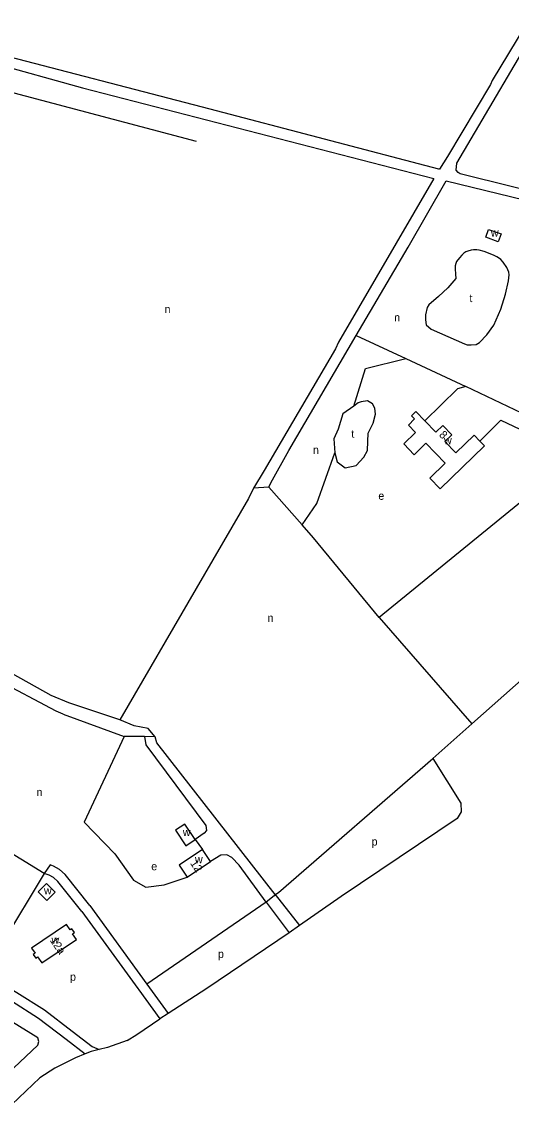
# Model space of a CAD drawing. Extents: x 156521 to 159067, y 384230 to 386095.
# Drawn here: x 158368 to 158613, y 384239 to 384783 of the extents above; entities that cross this region are included whole.
import ezdxf

# ---------------------------------------------------------------- set-up
doc = ezdxf.new("R2010")
doc.units = 0
for name, color, linetype in [('BLT_Basislijn', 7, 'Continuous'), ('BLT_Bebouwing', 7, 'Continuous'), ('BLT_Centroide', 7, 'Continuous'), ('BLT_Huisnummer', 7, 'Continuous')]:
    doc.layers.add(name, color=color, linetype=linetype)

msp = doc.modelspace()

# ---------------------------------------------------------------- linework, layer by layer
at = {"layer": 'BLT_Basislijn'}
for p, q in [((158352.64, 384750.74), (158455.21, 384723.61)), ((158535.23, 384626.42), (158559.94, 384614.94)), ((158559.94, 384614.94), (158589.98, 384600.98)), ((158650.46, 384571.96), (158589.98, 384600.98)), ((158537.65, 384593.29), (158536.19, 384592.74)), ((158536.19, 384592.74), (158533.96, 384591.17)), ((158639.35, 384561.14), (158546.61, 384485.51)), ((158489.11, 384559.04), (158483.85, 384550.1)), ((158491.46, 384550.64), (158483.85, 384550.1)), ((158508.09, 384531.79), (158491.46, 384550.64)), ((158513.81, 384525.32), (158508.09, 384531.79)), ((158546.61, 384485.51), (158513.81, 384525.32)), ((158455.16, 384500), (158416.95, 384434.38)), ((158546.61, 384485.51), (158592.98, 384432.27)), ((158592.98, 384432.27), (158655.78, 384487.93)), ((158416.95, 384434.38), (158391.54, 384442.78)), ((158388.72, 384437.21), (158419.17, 384425.97)), ((158573.58, 384415.07), (158592.98, 384432.27)), ((158429.32, 384425.97), (158419.17, 384425.97)), ((158434.62, 384425.77), (158429.32, 384425.97)), ((158379.14, 384357.53), (158354.03, 384372.8)), ((158454.66, 384374.5), (158458.38, 384369.51)), ((158490.08, 384343.23), (158501.59, 384327.81)), ((158494.68, 384347.02), (158506.82, 384331.47)), ((158506.82, 384331.47), (158501.59, 384327.81)), ((158426.42, 384299.39), (158437.05, 384284.91))]:
    msp.add_line(p, q, dxfattribs=at)
for points in [[(158342.81, 384770.73), (158333.64, 384773.36), (158283.17, 384786.22), (158282.77, 384787.06), (158335.72, 384877.79), (158631, 384801.39), (158631.05, 384800.83), (158627.73, 384794.49), (158603.23, 384753.88), (158602.28, 384751.89), (158580.79, 384715.97), (158576.88, 384709.55), (158576.56, 384709.5), (158462.13, 384739.64), (158349.17, 384768.98)], [(158736.06, 384689.06), (158733.97, 384685.58), (158724.47, 384677.61), (158719.79, 384675.59), (158715, 384675.59), (158591.18, 384706.23), (158587.23, 384707.3), (158586.12, 384707.91), (158585.24, 384709.01), (158585.48, 384712.56), (158630.6, 384789.27), (158635.77, 384798.67), (158636.48, 384799.41), (158637.85, 384799.54), (158660.96, 384793.85), (158752.07, 384770.33)], [(158352.67, 384762.86), (158398.26, 384750.21), (158574.08, 384704.89)], [(158574.08, 384704.89), (158526.41, 384623.05), (158524.75, 384619.77), (158489.11, 384559.04)], [(158535.23, 384626.42), (158561.09, 384670.52), (158580.13, 384703.71), (158664.3, 384683.31), (158653.02, 384664.92)], [(158491.46, 384550.64), (158492.42, 384552.8), (158501.54, 384568.98), (158535.23, 384626.42)], [(158533.96, 384591.17), (158539.78, 384609.9), (158559.94, 384614.94)], [(158589.98, 384600.98), (158585.79, 384599.85), (158569.58, 384583.81)], [(158524.51, 384567.78), (158525.65, 384563.34), (158529.66, 384560.33), (158535.13, 384561.44), (158538.92, 384565.56), (158540.86, 384568.91), (158541.04, 384573.49), (158541.2, 384577.64), (158543.72, 384582.59), (158544.82, 384587.18), (158544.56, 384590.11), (158543.26, 384592.27), (158540.76, 384593.83), (158537.65, 384593.29)], [(158533.96, 384591.17), (158528.53, 384587.34), (158526.11, 384579.64), (158524.07, 384574.86), (158524.51, 384567.78)], [(158597.08, 384573.54), (158607.52, 384584.17), (158644.87, 384566.51)], [(158508.09, 384531.79), (158515.56, 384542.46), (158524.51, 384567.78)], [(158483.85, 384550.1), (158481.31, 384544.91), (158455.16, 384500)], [(157930.85, 384516.53), (157966.23, 384498.78), (157998.05, 384481.98), (158036.93, 384459.43), (158098.19, 384426.71), (158139.42, 384404.83), (158176.28, 384383.04), (158191.55, 384374.9), (158226.78, 384355.64), (158247.56, 384344.81), (158267.27, 384335.72), (158293.91, 384325.39), (158315.6, 384317.66), (158330.79, 384311.93), (158345.17, 384304.36), (158362.89, 384293.81), (158376.39, 384285.18), (158390.18, 384274.78), (158399.69, 384267.38)], [(158391.54, 384442.78), (158382.68, 384446.47), (158359.21, 384459.6)], [(158388.72, 384437.21), (158385.22, 384438.59), (158354.81, 384454.73)], [(158434.62, 384425.77), (158431.14, 384429.93), (158424.17, 384431.35), (158416.95, 384434.38)], [(158419.17, 384425.97), (158399.23, 384383.24), (158414.56, 384367.36), (158423.79, 384354.16), (158430.06, 384350.65), (158439.11, 384351.85), (158450.74, 384355.71)], [(158429.32, 384425.97), (158429.96, 384421.88), (158459.95, 384381.43), (158460.4, 384379.01), (158459.1, 384377.76), (158454.66, 384374.5)], [(158494.68, 384347.02), (158435.45, 384422.79), (158434.62, 384425.77)], [(158494.68, 384347.02), (158496.36, 384347.97), (158573.58, 384415.07)], [(158573.58, 384415.07), (158587.55, 384392.67), (158587.71, 384388.37), (158585.64, 384385.09), (158527.73, 384346.01), (158506.82, 384331.47)], [(158490.08, 384343.23), (158476.6, 384361.62), (158473, 384365.44), (158470.54, 384366.92), (158467.42, 384366.69), (158462.39, 384363.57)], [(158402.05, 384341.55), (158389.64, 384357.01), (158386.78, 384359.54), (158383.78, 384361.25), (158382.15, 384361.8), (158379.14, 384357.53)], [(158379.14, 384357.53), (158358.37, 384322.88), (158351.24, 384316.92), (158344.38, 384316.23), (158332.84, 384316.5)], [(158398.07, 384338.51), (158386, 384353.55), (158383.86, 384355.45), (158381.73, 384356.66), (158379.14, 384357.53)], [(158490.08, 384343.23), (158430.55, 384302.21)], [(158494.68, 384347.02), (158494.21, 384346.3), (158490.08, 384343.23)], [(158398.07, 384338.51), (158425.98, 384300), (158426.42, 384299.39)], [(158402.05, 384341.55), (158430.55, 384302.21)], [(158501.59, 384327.81), (158460.48, 384300), (158441.16, 384287.56)], [(158332.84, 384316.5), (158347.62, 384308.73), (158365.52, 384298.06), (158379.25, 384289.29), (158393.22, 384278.75), (158403.13, 384271.03), (158406.63, 384269.51)], [(158363.96, 384260.34), (158376.01, 384271.73), (158376.42, 384273.48), (158376.02, 384275.36), (158353.95, 384288.95), (158332.21, 384300.36), (158306.22, 384311.84), (158298.23, 384313.32)], [(158430.55, 384302.21), (158441.16, 384287.56)], [(158420.72, 384274.05), (158425.42, 384276.97), (158437.05, 384284.91)], [(158441.16, 384287.56), (158437.05, 384284.91)], [(158420.72, 384274.05), (158410.88, 384270.55), (158406.63, 384269.51)], [(158399.69, 384267.38), (158394.76, 384265.44), (158384.48, 384260.27), (158376.97, 384255.3), (158359.46, 384238.69)], [(158406.63, 384269.51), (158402.67, 384268.55), (158399.69, 384267.38)]]:
    msp.add_lwpolyline(points, dxfattribs=at)
msp.add_lwpolyline([(158606.91, 384664.9), (158605.53, 384665.8), (158603.8, 384666.61), (158599.09, 384668.41), (158596.69, 384669.04), (158595.44, 384669.21), (158593.91, 384669.27), (158592.69, 384669.14), (158591.03, 384668.59), (158589.99, 384668.23), (158589, 384667.64), (158588, 384666.66), (158586.77, 384665.26), (158585.4, 384663.41), (158585.01, 384662.48), (158584.65, 384661.32), (158584.71, 384659.8), (158584.76, 384657.08), (158585.04, 384654.85), (158583.01, 384652.67), (158581.08, 384650.29), (158576.41, 384645.97), (158571.57, 384641.69), (158570.64, 384640.42), (158569.91, 384636.71), (158569.79, 384634.25), (158570.2, 384631.8), (158572.61, 384629.58), (158589.39, 384622.35), (158590.71, 384621.8), (158592.71, 384621.74), (158595.09, 384621.94), (158596.78, 384622.98), (158600.55, 384626.8), (158604.03, 384631.59), (158607.53, 384639.55), (158609.81, 384647.06), (158611.3, 384653.77), (158611.72, 384656.81), (158611.48, 384658.17), (158610.46, 384660.48), (158608.7, 384663.15), (158607.46, 384664.49)], close=True, dxfattribs=at)
at = {"layer": 'BLT_Bebouwing'}
for p, q in [((158462.39, 384363.57), (158458.38, 384369.51)), ((158450.74, 384355.71), (158462.39, 384363.57))]:
    msp.add_line(p, q, dxfattribs=at)
for points in [[(158606.25, 384673.28), (158599.98, 384675.52), (158601.38, 384679.44), (158607.65, 384677.2)], [(158454.66, 384374.5), (158449.53, 384382.18), (158444.9, 384379.1), (158450.04, 384371.41)], [(158380.31, 384352.47), (158376.22, 384348.33), (158380.52, 384344.08), (158384.61, 384348.23)]]:
    msp.add_lwpolyline(points, close=True, dxfattribs=at)
for points in [[(158569.58, 384583.81), (158565.05, 384588.47), (158562.84, 384586.33), (158564.4, 384584.72), (158561.27, 384581.69), (158564.87, 384577.98), (158558.93, 384572.22), (158564.12, 384566.87), (158570.05, 384572.63), (158579.75, 384562.63), (158571.98, 384555.09), (158577.15, 384549.77), (158599.29, 384571.24), (158597.08, 384573.54)], [(158575.04, 384578.18), (158569.58, 384583.81)], [(158594.11, 384576.61), (158585.06, 384567.83), (158579.57, 384573.5), (158583.03, 384576.85), (158578.51, 384581.53), (158575.04, 384578.18)], [(158597.08, 384573.54), (158594.11, 384576.61)], [(158458.38, 384369.51), (158446.73, 384361.65), (158450.74, 384355.71)], [(158372.9, 384320.17), (158374.58, 384317.68), (158373.71, 384317.09), (158374.97, 384315.23), (158375.89, 384315.85), (158377.94, 384312.81), (158395.27, 384324.54), (158393.31, 384327.42), (158394.24, 384328.05), (158392.98, 384329.92), (158392.12, 384329.34), (158390.34, 384331.97), (158372.9, 384320.17)]]:
    msp.add_lwpolyline(points, dxfattribs=at)

# ---------------------------------------------------------------- texts
at = {"layer": 'BLT_Centroide'}
for s, p in [('w', (158602.52, 384675.87)), ('t', (158591.79, 384643.14)), ('n', (158439.36, 384637.64)), ('n', (158554.17, 384633.5)), ('t', (158532.74, 384575.36)), ('w', (158579.11, 384572.09)), ('n', (158513.54, 384567.26)), ('e', (158546.25, 384544.31)), ('n', (158490.84, 384483.27)), ('n', (158375.33, 384396.22)), ('w', (158448.49, 384376.19)), ('p', (158542.88, 384371.49)), ('w', (158454.56, 384362.62)), ('e', (158432.69, 384359.14)), ('w', (158379.04, 384347.04)), ('w', (158382.81, 384322.38)), ('p', (158466.06, 384315.32)), ('p', (158392.09, 384303.92))]:
    msp.add_text(s, height=4, dxfattribs=at).set_placement(p)
at = {"layer": 'BLT_Huisnummer'}
for s, rotation, p in [('8', 315.5298, (158576.35, 384576.44)), ('12', 304.0096, (158451.99, 384362.62)), ('12a', 304.0096, (158381.84, 384324.08))]:
    msp.add_text(s, height=4, rotation=rotation, dxfattribs=at).set_placement(p)

doc.saveas('drawing.dxf')
